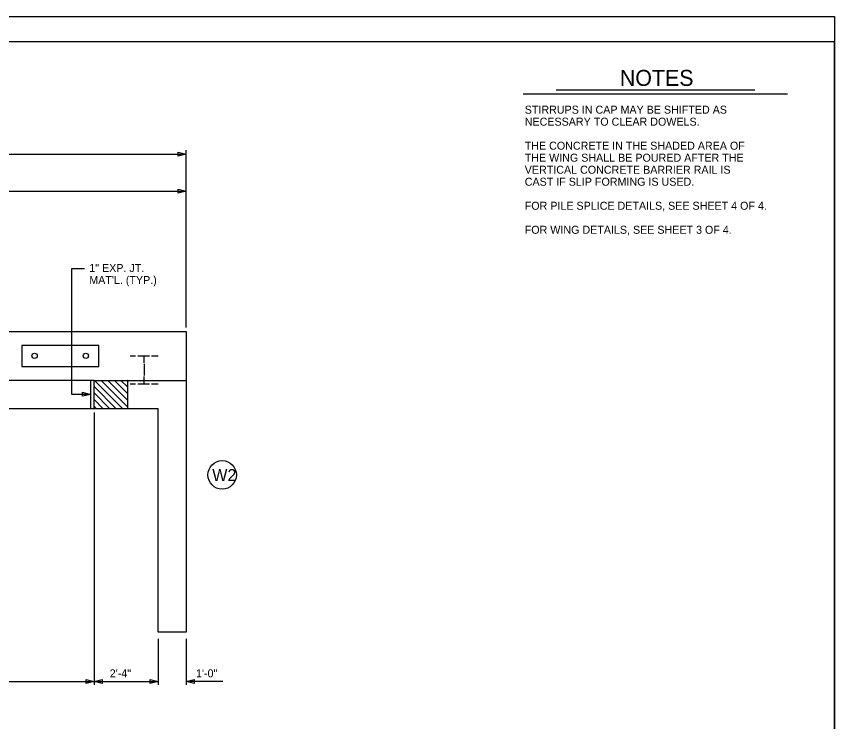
# Model space of a CAD drawing. Extents: x -41 to 251, y -169 to 237.
# Drawn here: x 46.48 to 75.71, y -25.28 to -0.09 of the extents above; entities that cross this region are included whole.
import ezdxf

# ---------------------------------------------------------------- set-up
doc = ezdxf.new("R2010")
doc.units = 0
for name, color, linetype in [('Arrowhead Terminators', 7, 'Continuous'), ('Arrowhead Terminators CELL', 7, 'Continuous'), ('Dimension Lines', 7, 'Continuous'), ('Mis Object Lines', 7, 'Continuous'), ('Miscellaneous Lines', 7, 'Continuous'), ('Plan Sheet CELL', 7, 'Continuous'), ('Plot Shape CELL', 7, 'Continuous'), ('Rebar Lines', 7, 'Continuous'), ('Subtitle Text', 7, 'Continuous'), ('Text', 7, 'Continuous'), ('Title Text', 7, 'Continuous')]:
    doc.layers.add(name, color=color, linetype=linetype)

msp = doc.modelspace()

# ---------------------------------------------------------------- linework, layer by layer
at = {"layer": 'Arrowhead Terminators'}
for points in [[(52.263, -4.933), (52.549, -5.005), (52.263, -5.076)], [(52.263, -6.264), (52.549, -6.336), (52.263, -6.407)], [(48.971, -23.767), (49.257, -23.838), (48.971, -23.91)], [(49.543, -23.91), (49.257, -23.838), (49.543, -23.767)], [(51.263, -23.767), (51.549, -23.838), (51.263, -23.91)], [(52.835, -23.91), (52.549, -23.838), (52.835, -23.767)]]:
    msp.add_lwpolyline(points, close=True, dxfattribs=at)
at = {"layer": 'Arrowhead Terminators CELL'}
msp.add_lwpolyline([(49.132, -13.587), (48.846, -13.658), (48.846, -13.515)], close=True, dxfattribs=at)
at = {"layer": 'Dimension Lines'}
for p, q in [((52.549, -11.194), (52.549, -4.869)), ((13.549, -5.005), (52.549, -5.005)), ((33.049, -6.336), (52.549, -6.336)), ((48.465, -13.587), (48.465, -9.087)), ((48.465, -9.087), (48.915, -9.087)), ((49.257, -13.087), (49.132, -13.087)), ((49.132, -13.087), (49.132, -14.087)), ((49.257, -14.087), (49.257, -13.087)), ((49.132, -13.587), (48.465, -13.587)), ((49.132, -14.087), (49.257, -14.087)), ((49.257, -14.23), (49.257, -23.963)), ((51.549, -22.324), (51.549, -23.963)), ((52.549, -22.324), (52.549, -23.963)), ((33.049, -23.838), (49.257, -23.838)), ((49.257, -23.838), (51.549, -23.838)), ((53.861, -23.838), (52.549, -23.838))]:
    msp.add_line(p, q, dxfattribs=at)
msp.add_circle((53.833, -16.464), 0.509, dxfattribs=at)
at = {"layer": 'Mis Object Lines'}
for p, q in [((33.049, -11.337), (52.549, -11.337)), ((52.549, -11.337), (52.549, -13.087)), ((49.257, -13.087), (16.84, -13.087)), ((49.257, -14.087), (49.257, -13.087)), ((49.257, -13.087), (52.549, -13.087)), ((50.276, -14.087), (49.276, -13.087)), ((50.465, -14.04), (49.511, -13.087)), ((50.465, -13.805), (49.747, -13.087)), ((50.465, -13.569), (49.983, -13.087)), ((50.465, -13.333), (50.218, -13.087)), ((50.465, -13.098), (50.454, -13.087)), ((50.465, -14.087), (50.465, -13.087)), ((52.549, -13.087), (52.549, -22.087)), ((50.04, -14.087), (49.257, -13.304)), ((49.804, -14.087), (49.257, -13.539)), ((49.568, -14.087), (49.257, -13.775)), ((49.333, -14.087), (49.257, -14.011)), ((33.049, -14.087), (51.549, -14.087)), ((51.549, -22.087), (51.549, -14.087)), ((52.549, -22.087), (51.549, -22.087))]:
    msp.add_line(p, q, dxfattribs=at)
at = {"layer": 'Miscellaneous Lines'}
msp.add_lwpolyline([(46.674, -12.587), (49.424, -12.587), (49.424, -11.837), (46.674, -11.837)], close=True, dxfattribs=at)
at = {"layer": 'Plan Sheet CELL'}
for p, q in [((75.715, -0.087), (75.715, -0.087)), ((2.414, -0.989), (75.694, -0.989)), ((75.694, -0.989), (75.694, -49.079))]:
    msp.add_line(p, q, dxfattribs=at)
at = {"layer": 'Plot Shape CELL'}
msp.add_lwpolyline([(0, -0.087), (75.715, -0.087), (75.715, -50.467), (0, -50.467)], close=True, dxfattribs=at)
at = {"layer": 'Rebar Lines'}
for points in [[(50.546, -12.211), (50.737, -12.211)], [(50.824, -12.211), (51.232, -12.211)], [(51.049, -12.459), (51.049, -12.212)], [(51.303, -12.211), (51.547, -12.211)], [(51.049, -12.498), (51.049, -12.711)], [(51.049, -12.712), (51.049, -12.911)], [(51.049, -13.212), (51.049, -12.954)], [(50.546, -13.212), (50.737, -13.212)], [(50.824, -13.212), (51.232, -13.212)], [(51.303, -13.212), (51.547, -13.212)]]:
    msp.add_lwpolyline(points, dxfattribs=at)
for centre in [(47.132, -12.212), (48.965, -12.212)]:
    msp.add_circle(centre, 0.0938, dxfattribs=at)
at = {"layer": 'Title Text'}
for p, q in [((64.592, -2.855), (74.027, -2.855)), ((65.76, -2.712), (72.859, -2.712))]:
    msp.add_line(p, q, dxfattribs=at)

# ---------------------------------------------------------------- texts
at = {"layer": 'Subtitle Text'}
for s, height, p in [('STIRRUPS IN CAP MAY BE SHIFTED AS', 0.286, (64.643, -3.562)), ('NECESSARY TO CLEAR DOWELS.', 0.286, (64.643, -3.991)), ('THE CONCRETE IN THE SHADED AREA OF', 0.286, (64.643, -4.849)), ('THE WING SHALL BE POURED AFTER THE', 0.286, (64.643, -5.278)), ('VERTICAL CONCRETE BARRIER RAIL IS', 0.286, (64.643, -5.707)), ('CAST IF SLIP FORMING IS USED.', 0.286, (64.643, -6.136)), ('FOR PILE SPLICE DETAILS, SEE SHEET 4 OF 4.', 0.286, (64.643, -6.994)), ('FOR WING DETAILS, SEE SHEET 3 OF 4.', 0.286, (64.643, -7.852)), ('W2', 0.429, (53.479, -16.687))]:
    msp.add_text(s, height=height, dxfattribs=at).set_placement(p)
at = {"layer": 'Text'}
for s, p in [('1" EXP. JT.', (49.086, -9.217)), ("MAT'L. (TYP.)", (49.086, -9.646)), ('2\'-4"', (49.817, -23.695)), ('1\'-0"', (52.899, -23.695))]:
    msp.add_text(s, height=0.286, dxfattribs=at).set_placement(p)
at = {"layer": 'Title Text'}
msp.add_text('NOTES', height=0.5714, dxfattribs=at).set_placement((68.041, -2.57))

doc.saveas('drawing.dxf')
